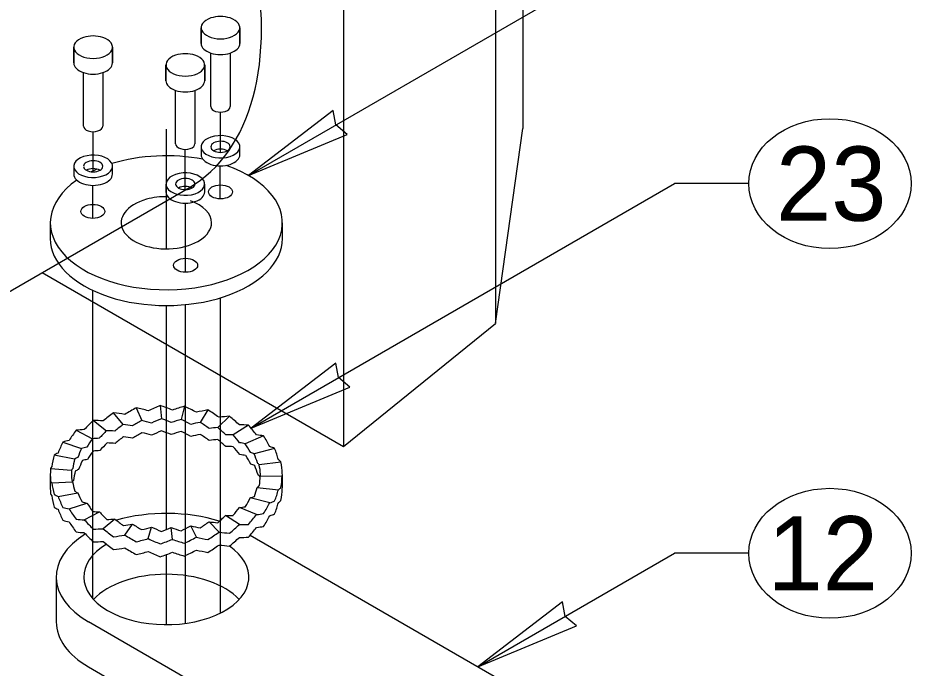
# Model space of a CAD drawing. Extents: x 99862 to 104211, y 98939 to 105076.
# Drawn here: x 102045.1 to 102237.6, y 101616.6 to 101756.7 of the extents above; entities that cross this region are included whole.
import ezdxf

# ---------------------------------------------------------------- set-up
doc = ezdxf.new("R2010")
doc.units = 0
for name, color, linetype in [('Level 11', 7, 'Continuous'), ('Level 12', 7, 'Continuous'), ('Level 15', 7, 'Continuous'), ('Level 19', 7, 'Continuous'), ('Level 20', 7, 'Continuous'), ('Level 24', 7, 'Continuous'), ('Level 26', 7, 'Continuous')]:
    doc.layers.add(name, color=color, linetype=linetype)

msp = doc.modelspace()

# ---------------------------------------------------------------- linework, layer by layer
at = {"layer": 'Level 11'}
for p, q in [((102084.64, 101751.2), (102084.64, 101754.6)), ((102084.64, 101754.6), (102084.64, 101751.2)), ((102092.98, 101754.6), (102092.98, 101751.2)), ((102092.98, 101751.2), (102092.98, 101754.6)), ((102057.2, 101747), (102057.2, 101750.4)), ((102057.2, 101750.4), (102057.2, 101747)), ((102065.54, 101750.4), (102065.54, 101747)), ((102065.54, 101747), (102065.54, 101750.4)), ((102086.73, 101737.59), (102086.73, 101749.12)), ((102090.89, 101749.12), (102090.89, 101737.59)), ((102077.06, 101743.17), (102077.06, 101746.58)), ((102077.06, 101746.58), (102077.06, 101743.17)), ((102085.4, 101746.58), (102085.4, 101743.17)), ((102085.4, 101743.17), (102085.4, 101746.58)), ((102059.29, 101733.39), (102059.29, 101744.91)), ((102063.45, 101744.91), (102063.45, 101733.39)), ((102079.15, 101729.57), (102079.15, 101741.09)), ((102083.31, 101741.09), (102083.31, 101729.57)), ((102084.64, 101728.93), (102084.64, 101727.23)), ((102092.98, 101727.23), (102092.98, 101728.93)), ((102057.2, 101724.73), (102057.2, 101723.03)), ((102065.54, 101723.03), (102065.54, 101724.73)), ((102077.06, 101720.9), (102077.06, 101719.2)), ((102085.4, 101719.2), (102085.4, 101720.9)), ((102052.14, 101712.56), (102052.14, 101709.16)), ((102102.14, 101709.16), (102102.14, 101712.56))]:
    msp.add_line(p, q, dxfattribs=at)
for centre, major_axis, start_param, end_param in [((102088.81, 101754.6), (-4.17, 0), 5.235988, 10.471976), ((102088.81, 101754.6), (-4.17, 0), 4.18879, 5.235988), ((102061.37, 101750.4), (-4.17, 0), 5.235988, 10.471976), ((102061.37, 101750.4), (-4.17, 0), 4.18879, 5.235988), ((102088.81, 101751.2), (-4.17, 0), 6.283185, 9.424778), ((102081.23, 101746.58), (-4.17, 0), 5.235988, 10.471976), ((102081.23, 101746.58), (-4.17, 0), 4.18879, 5.235988), ((102061.37, 101747), (-4.17, 0), 6.283185, 9.424778), ((102081.23, 101743.17), (-4.17, 0), 6.283185, 9.424778), ((102088.81, 101737.59), (-2.08, 0), 6.283129, 9.424778), ((102061.37, 101733.39), (-2.08, 0), 6.283129, 9.424778), ((102088.81, 101728.93), (-4.17, 0), 0.321913, 6.60445), ((102081.23, 101729.57), (-2.08, 0), 6.283129, 9.424778), ((102088.81, 101728.93), (-2.08, 0), 0.014662, 6.283185), ((102061.37, 101724.73), (-4.17, 0), 0.321913, 6.60445), ((102077.14, 101712.56), (-25, 0), 4.39277, 5.200653), ((102088.81, 101727.23), (-4.17, 0), 0, 3.141593), ((102088.81, 101727.23), (-2.08, 0), 3.926991, 5.497787), ((102061.37, 101724.73), (-2.08, 0), 0.014662, 6.283185), ((102077.14, 101712.56), (-25, 0), 5.593856, 10.454374), ((102061.37, 101723.03), (-2.08, 0), 3.926991, 5.497787), ((102077.14, 101712.56), (-25, 0), 5.35311, 5.417542), ((102081.23, 101720.9), (-4.17, 0), 0.321913, 6.60445), ((102061.37, 101723.03), (-4.17, 0), 0, 3.141593), ((102081.23, 101720.9), (-2.08, 0), 0.014662, 6.283185), ((102081.23, 101719.2), (-2.08, 0), 3.926991, 5.497787), ((102077.14, 101712.56), (9.74, 0), 2.024427, 6.283185), ((102077.14, 101712.56), (9.74, 0), 1.538326, 2.024427), ((102081.23, 101719.2), (-4.17, 0), 0, 3.141593), ((102077.14, 101712.56), (9.74, 0), 0, 1.006138), ((102077.14, 101709.16), (-25, 0), 0, 3.141593)]:
    msp.add_ellipse(centre, major_axis=major_axis, ratio=0.57735, start_param=start_param, end_param=end_param, dxfattribs=at)
for centre in [(102088.81, 101719.21), (102061.3, 101715.01), (102081.29, 101703.4)]:
    msp.add_ellipse(centre, major_axis=(-2.6, 0), ratio=0.57735, dxfattribs=at)
at = {"layer": 'Level 12'}
for p, q in [((102197.14, 101586.33), (102095.17, 101645.2)), ((102053.42, 101636.24), (102053.42, 101626.55)), ((102179.92, 101557.53), (102060.37, 101626.55)), ((102060.37, 101616.87), (102180.23, 101547.66))]:
    msp.add_line(p, q, dxfattribs=at)
for centre, major_axis, start_param, end_param in [((102077.14, 101636.24), (-23.72, 0), 4.210368, 5.182538), ((102077.14, 101636.24), (-23.72, 0), 5.538106, 7.068583), ((102077.14, 101636.24), (-17.79, 0), 5.523421, 10.132628), ((102077.14, 101626.55), (17.79, 0), 0.490883, 2.65071), ((102077.14, 101626.55), (23.72, 0), 3.141593, 3.926991)]:
    msp.add_ellipse(centre, major_axis=major_axis, ratio=0.57735, start_param=start_param, end_param=end_param, dxfattribs=at)
at = {"layer": 'Level 15'}
for p, q in [((102094.82, 101722.77), (102186.63, 101775.77)), ((102088.74, 101736.39), (102088.74, 101727.73)), ((102061.3, 101732.19), (102061.3, 101723.53)), ((102077.14, 101706.93), (102077.14, 101732.7)), ((102081.16, 101728.36), (102081.16, 101719.7)), ((102088.74, 101717.71), (102088.74, 101724.83)), ((102061.3, 101713.5), (102061.3, 101720.62)), ((102095.39, 101668.31), (102186.63, 101720.99)), ((102202.63, 101720.99), (102186.63, 101720.99)), ((102081.29, 101701.89), (102081.29, 101716.8)), ((102061.3, 101631.56), (102061.3, 101697.99)), ((102088.81, 101628.48), (102088.81, 101696.39)), ((102077.14, 101646.45), (102077.14, 101694.72)), ((102081.29, 101626.25), (102081.29, 101694.92)), ((102077.14, 101625.96), (102077.14, 101641.07)), ((102144.24, 101616.87), (102186.63, 101641.34)), ((102202.63, 101641.34), (102186.63, 101641.34))]:
    msp.add_line(p, q, dxfattribs=at)
for points in [[(102094.82, 101722.77), (102116.08, 101731.59), (102113.68, 101733.65), (102113.1, 101736.77)], [(102095.39, 101668.31), (102116.66, 101677.14), (102114.25, 101679.2), (102113.67, 101682.31)], [(102144.24, 101616.87), (102165.51, 101625.7), (102163.1, 101627.75), (102162.52, 101630.87)]]:
    msp.add_lwpolyline(points, close=True, dxfattribs=at)
at = {"layer": 'Level 19'}
for p, q in [((102148.09, 101690.86), (102153.96, 101732.86)), ((102115.32, 101664.37), (102148.09, 101690.86))]:
    msp.add_line(p, q, dxfattribs=at)
at = {"layer": 'Level 20'}
for centre in [(102220.13, 101720.99), (102220.13, 101641.34)]:
    msp.add_ellipse(centre, major_axis=(-17.5, 0), ratio=0.8, dxfattribs=at)
at = {"layer": 'Level 24'}
for p, q in [((102075.83, 101673.17), (102076.07, 101670.34)), ((102067.86, 101669.1), (102065.79, 101671.62)), ((102070.67, 101672.7), (102071.86, 101669.97)), ((102081.05, 101673.01), (102080.33, 101670.19)), ((102086.1, 101672.23), (102084.44, 101669.54)), ((102061.41, 101669.97), (102064.26, 101667.76)), ((102088.21, 101668.42), (102090.75, 101670.86)), ((102057.71, 101667.84), (102061.23, 101666.02)), ((102094.83, 101668.95), (102091.51, 101666.86)), ((102098.11, 101666.62), (102094.16, 101664.95)), ((102054.87, 101665.31), (102058.89, 101663.95)), ((102100.48, 101663.93), (102096.08, 101662.77)), ((102057.36, 101661.64), (102052.99, 101662.49)), ((102101.83, 101661.01), (102097.16, 101660.4)), ((102052.14, 101658.27), (102052.14, 101655.5)), ((102056.7, 101659.2), (102052.18, 101659.51)), ((102097.38, 101657.96), (102102.11, 101658)), ((102097.46, 101657.96), (102097.44, 101658.31)), ((102102.14, 101655.5), (102102.14, 101658.27)), ((102052.45, 101656.5), (102056.94, 101656.73)), ((102056.73, 101657.59), (102056.75, 101657.16)), ((102053.8, 101653.58), (102058.07, 101654.35)), ((102096.71, 101655.54), (102101.29, 101655.02)), ((102056.18, 101650.89), (102060.03, 101652.16)), ((102099.42, 101652.2), (102095.19, 101653.26)), ((102059.46, 101648.55), (102062.73, 101650.25)), ((102096.57, 101649.67), (102092.89, 101651.21)), ((102066.06, 101648.71), (102063.53, 101646.64)), ((102086.35, 101648.14), (102088.49, 101645.89)), ((102092.88, 101647.54), (102089.9, 101649.48)), ((102068.18, 101645.28), (102069.86, 101647.61)), ((102073.23, 101644.5), (102073.97, 101646.99)), ((102078.45, 101644.34), (102078.2, 101646.87)), ((102083.61, 101644.81), (102082.39, 101647.26))]:
    msp.add_line(p, q, dxfattribs=at)
for centre, major_axis, ratio, start_param, end_param in [((102077.14, 101657.78), (23.99, 13.35), 0.527399, 1.337713, 1.442432), ((102077.14, 101657.78), (-24.17, 12.86), 0.497899, 4.918981, 5.0237), ((102077.14, 101657.78), (23.09, 14.75), 0.650745, 1.648089, 1.752809), ((102077.14, 101657.78), (-24.67, 10.41), 0.386234, 5.240379, 5.345098), ((102077.14, 101657.78), (23.57, 14.17), 0.588004, 1.492908, 1.597627), ((102077.14, 101657.78), (-24.46, 11.73), 0.440657, 5.077658, 5.182378), ((102077.14, 101657.78), (24.32, 12.32), 0.468967, 1.180574, 1.285294), ((102077.14, 101657.78), (-23.79, 13.78), 0.557438, 4.763018, 4.867737), ((102077.14, 101657.78), (24.58, 11.09), 0.413044, 1.020027, 1.124747), ((102077.14, 101657.78), (-23.34, 14.49), 0.6191, 4.608118, 4.712837), ((102077.14, 101657.78), (22.56, 15.04), 0.715795, 1.806331, 1.911051), ((102077.14, 101657.78), (-24.82, 8.91), 0.335596, 5.40825, 5.512969), ((102077.09, 101657.78), (-18.71, -11.62), 0.598244, 4.622152, 4.729007), ((102077.09, 101657.81), (20.39, -9.75), 0.429328, 1.924562, 2.027518), ((102077.09, 101657.77), (-19.05, -10.93), 0.535491, 4.465396, 4.572456), ((102077.09, 101657.81), (20.16, -10.74), 0.484995, 1.769848, 1.872378), ((102077.09, 101657.77), (-19.34, -10.08), 0.475083, 4.306477, 4.413646), ((102077.09, 101657.81), (19.84, -11.56), 0.543025, 1.61865, 1.720863), ((102077.09, 101657.77), (-19.58, -9.08), 0.417364, 4.144071, 4.251256), ((102077.09, 101657.81), (19.43, -12.2), 0.603283, 1.46947, 1.571493), ((102077.14, 101657.78), (24.76, 9.68), 0.360362, 0.8552, 0.959575), ((102077.14, 101657.78), (-22.85, 14.83), 0.683288, 4.448984, 4.554049), ((102077.14, 101657.78), (22.09, 14.93), 0.783391, 1.973965, 2.078685), ((102077.14, 101657.78), (-24.91, 7.25), 0.290225, 5.582091, 5.686811), ((102077.09, 101657.79), (-17.89, -12.4), 0.730894, 4.937429, 5.043598), ((102077.09, 101657.8), (20.61, -7.34), 0.327453, 2.249442, 2.353465), ((102077.09, 101657.78), (-18.31, -12.12), 0.663313, 4.778515, 4.885072), ((102077.09, 101657.81), (20.54, -8.62), 0.376508, 2.084067, 2.18753), ((102077.19, 101655.99), (-18.89, -11.29), 0.566582, 4.65521, 4.761435), ((102077.2, 101655.96), (20.47, -9.2), 0.402516, 1.905515, 2.007935), ((102077.19, 101656), (-19.21, -10.52), 0.50498, 4.498422, 4.604994), ((102077.2, 101655.96), (20.29, -10.27), 0.456845, 1.749535, 1.851681), ((102077.19, 101656), (-19.47, -9.6), 0.445851, 4.33846, 4.445308), ((102077.2, 101655.96), (20.01, -11.17), 0.51373, 1.59739, 1.699385), ((102077.09, 101657.77), (-19.77, -7.94), 0.363082, 3.977435, 4.084195), ((102077.09, 101657.81), (18.96, -12.55), 0.66635, 1.317558, 1.419881), ((102077.14, 101657.78), (24.87, 8.06), 0.313871, 0.683714, 0.78878), ((102077.14, 101657.78), (-22.31, 15.05), 0.749264, 4.290148, 4.394522), ((102077.14, 101657.78), (-24.96, 5.45), 0.252109, 5.762237, 5.866957), ((102077.09, 101657.79), (-17.52, -12.37), 0.801277, 5.105481, 5.211183), ((102077.09, 101657.8), (20.62, -5.93), 0.283588, 2.42148, 2.526083), ((102077.19, 101655.99), (-18.51, -11.89), 0.630481, 4.810354, 4.916165), ((102077.2, 101655.96), (20.58, -7.99), 0.351433, 2.06656, 2.169358), ((102077.19, 101656), (-19.68, -8.52), 0.389728, 4.174109, 4.281154), ((102077.2, 101655.95), (19.64, -11.91), 0.572873, 1.447674, 1.549653), ((102077.19, 101656), (-19.85, -7.31), 0.337596, 4.00437, 4.11153), ((102077.2, 101655.95), (19.19, -12.45), 0.63428, 1.299034, 1.400798), ((102077.09, 101657.77), (-19.92, -6.63), 0.315205, 3.804372, 3.911664), ((102077.09, 101657.81), (18.4, -12.84), 0.731211, 1.168256, 1.269974), ((102077.14, 101657.78), (24.94, 6.37), 0.270119, 0.507084, 0.611804), ((102077.14, 101657.78), (-21.94, 14.64), 0.818147, 4.112606, 4.217325), ((102077.14, 101657.78), (21.92, 14.08), 0.853385, 2.16914, 2.27386), ((102077.09, 101657.79), (-17.45, -11.66), 0.874367, 5.304524, 5.409696), ((102077.09, 101657.79), (20.58, -4.42), 0.246838, 2.600485, 2.705657), ((102077.2, 101655.97), (20.61, -5.19), 0.264186, 2.407555, 2.51132), ((102077.19, 101655.99), (-18.1, -12.29), 0.696771, 4.966104, 5.071448), ((102077.2, 101655.97), (20.62, -6.65), 0.304762, 2.23369, 2.336945), ((102077.19, 101656), (-19.98, -5.95), 0.29281, 3.828548, 3.936073), ((102077.2, 101655.96), (18.7, -12.68), 0.698549, 1.144423, 1.247134), ((102077.09, 101657.77), (-20.04, -5.26), 0.270295, 3.626269, 3.732988), ((102077.09, 101657.81), (17.89, -12.71), 0.799628, 1.006665, 1.108934), ((102077.14, 101657.78), (24.98, 4.51), 0.236491, 0.323887, 0.428607), ((102077.14, 101657.78), (-22.18, 12.98), 0.888613, 3.882951, 3.987671), ((102077.14, 101657.78), (22.99, 10.64), 0.922162, 2.476441, 2.581161), ((102077.14, 101657.78), (-24.99, 3.53), 0.223561, 5.948263, 6.052982), ((102077.09, 101657.8), (-18.93, -7.75), 0.945022, 5.676186, 5.780789), ((102077.09, 101657.79), (20.52, -2.82), 0.219467, 2.786003, 2.891705), ((102077.19, 101655.98), (20.55, -3.63), 0.231835, 2.588195, 2.692495), ((102077.19, 101655.98), (-17.69, -12.44), 0.765721, 5.126739, 5.231572), ((102077.19, 101656), (-20.1, -4.52), 0.251785, 3.646437, 3.75321), ((102077.2, 101655.96), (18.13, -12.83), 0.765007, 0.991605, 1.094336), ((102077.09, 101657.77), (-20.15, -3.75), 0.235717, 3.442095, 3.548503), ((102077.09, 101657.81), (17.65, -11.94), 0.871239, 0.815178, 0.917775), ((102077.14, 101657.78), (-25, 1.53), 0.206802, 6.138761, 6.243481), ((102077.09, 101657.79), (20.44, -1.17), 0.203679, 2.976608, 3.082777), ((102077.19, 101655.98), (-17.41, -12.14), 0.837545, 5.303627, 5.407926), ((102077.19, 101655.99), (-20.2, -2.97), 0.222374, 3.458633, 3.565603), ((102077.2, 101655.96), (17.71, -12.45), 0.835077, 0.818447, 0.921647), ((102077.09, 101657.78), (-20.25, -2.16), 0.212017, 3.253154, 3.35918), ((102077.09, 101657.8), (18.83, -8.32), 0.941831, 0.468891, 0.57191), ((102077.14, 101657.78), (24.99, 2.54), 0.213589, 0.135385, 0.240105), ((102077.14, 101657.78), (-24.57, 4.88), 0.947565, 3.380043, 3.484762), ((102077.14, 101657.78), (-24.57, 4.88), 0.947565, 0.13373, 0.23845), ((102077.09, 101657.8), (18.83, -8.32), 0.941831, 3.50935, 3.613372), ((102077.2, 101655.97), (-17.81, -10.59), 0.911117, 5.546488, 5.650253), ((102077.19, 101655.98), (20.48, -2), 0.210005, 2.774764, 2.879597), ((102077.19, 101655.99), (-20.3, -1.34), 0.20486, 3.266696, 3.373414), ((102077.09, 101657.8), (-18.93, -7.75), 0.945022, 2.63741, 2.740916), ((102077.2, 101655.96), (17.89, -10.9), 0.907593, 0.67037, 0.687271), ((102077.09, 101657.78), (20.35, 0.51), 0.201051, 6.203047, 6.308631), ((102077.14, 101657.78), (22.99, 10.64), 0.922162, 5.722754, 5.827474), ((102077.14, 101657.78), (25, 0.51), 0.203365, 6.226668, 6.331388), ((102077.14, 101657.78), (25, 0.51), 0.203365, 3.189796, 3.294515), ((102077.14, 101657.78), (-22.18, 12.98), 0.888613, 0.636639, 0.741359), ((102077.09, 101657.78), (20.35, 0.51), 0.201051, 3.169927, 3.276484), ((102077.19, 101655.99), (20.39, -0.33), 0.200662, 2.965412, 3.034193), ((102077.09, 101657.81), (17.65, -11.94), 0.871239, 3.857172, 3.960635), ((102077.09, 101657.79), (20.44, -1.17), 0.203679, 6.011323, 6.116415), ((102077.14, 101655.99), (-24.57, -4.88), 0.947565, 6.097095, 6.149455), ((102077.14, 101655.99), (-25, -1.53), 0.206802, 0.039705, 0.144424), ((102077.14, 101657.78), (24.99, 2.54), 0.213589, 3.381698, 3.486418), ((102077.09, 101657.78), (-20.25, -2.16), 0.212017, 0.221451, 0.328307), ((102077.09, 101657.81), (17.89, -12.71), 0.799628, 4.049974, 4.152929), ((102077.09, 101657.79), (-17.45, -11.66), 0.874367, 2.267499, 2.37153), ((102077.14, 101657.78), (21.92, 14.08), 0.853385, 5.415452, 5.520172), ((102077.14, 101657.78), (-25, 1.53), 0.206802, 2.892449, 2.997168), ((102077.14, 101655.99), (-24.57, -4.88), 0.947565, 2.798423, 2.903143), ((102077.14, 101655.99), (25, -0.51), 0.203365, 6.234982, 6.287342), ((102077.14, 101655.99), (22.99, -10.64), 0.922162, 3.702024, 3.806744), ((102077.14, 101657.78), (-21.94, 14.64), 0.818147, 0.866293, 0.971013), ((102077.09, 101657.77), (-20.15, -3.75), 0.235717, 0.411581, 0.518641), ((102077.09, 101657.81), (18.4, -12.84), 0.731211, 4.212591, 4.315121), ((102077.09, 101657.79), (-17.52, -12.37), 0.801277, 2.070195, 2.174763), ((102077.09, 101657.79), (20.52, -2.82), 0.219467, 5.822424, 5.926992), ((102077.14, 101657.78), (22.09, 14.93), 0.783391, 5.220277, 5.324997), ((102077.14, 101657.78), (-24.99, 3.53), 0.223561, 2.70195, 2.80667), ((102077.14, 101655.99), (-22.18, -12.98), 0.888613, 2.295514, 2.400234), ((102077.14, 101655.99), (24.99, -2.54), 0.213589, 6.04308, 6.1478), ((102077.14, 101655.99), (-24.99, -3.53), 0.223561, 0.230203, 0.334923), ((102077.14, 101655.99), (21.92, -14.08), 0.853385, 4.009326, 4.114045), ((102077.14, 101657.78), (24.98, 4.51), 0.236491, 3.570199, 3.674919), ((102077.14, 101657.78), (-22.31, 15.05), 0.749264, 1.043836, 1.148555), ((102077.09, 101657.77), (-20.04, -5.26), 0.270295, 0.596668, 0.703484), ((102077.09, 101657.81), (18.96, -12.55), 0.66635, 4.362228, 4.464795), ((102077.09, 101657.79), (-17.89, -12.4), 0.730894, 1.903791, 2.008884), ((102077.09, 101657.79), (20.58, -4.42), 0.246838, 5.638651, 5.742681), ((102077.14, 101655.99), (-24.96, -5.45), 0.252109, 0.416228, 0.520948), ((102077.14, 101655.99), (22.09, -14.93), 0.783391, 4.204501, 4.308875), ((102077.14, 101657.78), (24.94, 6.37), 0.270119, 3.753396, 3.857771), ((102077.14, 101657.78), (-22.85, 14.83), 0.683288, 1.202326, 1.307392), ((102077.09, 101657.77), (-19.92, -6.63), 0.315205, 0.775717, 0.883239), ((102077.09, 101657.81), (19.43, -12.2), 0.603283, 4.515147, 4.616833), ((102077.09, 101657.78), (-18.71, -11.62), 0.598244, 1.591279, 1.697305), ((102077.09, 101657.8), (20.61, -7.34), 0.327453, 5.290905, 5.393923), ((102077.09, 101657.78), (-18.31, -12.12), 0.663313, 1.746368, 1.851952), ((102077.09, 101657.8), (20.62, -5.93), 0.283588, 5.461353, 5.564858), ((102077.14, 101657.78), (22.56, 15.04), 0.715795, 5.052644, 5.157364), ((102077.14, 101657.78), (-24.96, 5.45), 0.252109, 2.515925, 2.620645), ((102077.14, 101655.99), (-21.94, -14.64), 0.818147, 2.06586, 2.17058), ((102077.14, 101655.99), (24.98, -4.51), 0.236491, 5.854579, 5.959298), ((102077.14, 101657.78), (24.87, 8.06), 0.313871, 3.930372, 4.035437), ((102077.14, 101657.78), (-23.34, 14.49), 0.6191, 1.362151, 1.466525), ((102077.09, 101657.77), (-19.77, -7.94), 0.363082, 0.948373, 1.055486), ((102077.09, 101657.81), (19.84, -11.56), 0.543025, 4.663917, 4.765887), ((102077.09, 101657.77), (-19.58, -9.08), 0.417364, 1.115309, 1.222265), ((102077.09, 101657.81), (20.16, -10.74), 0.484995, 4.814659, 4.916713), ((102077.09, 101657.77), (-19.34, -10.08), 0.475083, 1.277326, 1.384046), ((102077.09, 101657.81), (20.39, -9.75), 0.429328, 4.968557, 5.070826), ((102077.09, 101657.77), (-19.05, -10.93), 0.535491, 1.435534, 1.541941), ((102077.09, 101657.81), (20.54, -8.62), 0.376508, 5.126927, 5.229524), ((102077.14, 101657.78), (23.09, 14.75), 0.650745, 4.894402, 4.999121), ((102077.14, 101657.78), (-24.91, 7.25), 0.290225, 2.335779, 2.440499), ((102077.14, 101655.99), (-22.31, -15.05), 0.749264, 1.888318, 1.993037), ((102077.14, 101655.99), (24.94, -6.37), 0.270119, 5.671382, 5.776101), ((102077.14, 101655.99), (-24.91, -7.21), 0.292084, 0.595944, 0.70101), ((102077.14, 101655.99), (22.6, -14.92), 0.716006, 4.368664, 4.47373), ((102077.14, 101657.78), (24.76, 9.68), 0.360362, 4.101167, 4.205887), ((102077.14, 101657.78), (-23.79, 13.78), 0.557438, 1.516705, 1.621425), ((102077.14, 101657.78), (24.58, 11.09), 0.413044, 4.266339, 4.371059), ((102077.14, 101657.78), (-24.17, 12.86), 0.497899, 1.672668, 1.777388), ((102077.14, 101657.78), (24.32, 12.32), 0.468967, 4.426886, 4.531606), ((102077.14, 101657.78), (-24.46, 11.73), 0.440657, 1.831346, 1.936066), ((102077.14, 101657.78), (23.99, 13.35), 0.527399, 4.584025, 4.688745), ((102077.14, 101657.78), (-24.67, 10.41), 0.386234, 1.994066, 2.098786), ((102077.14, 101657.78), (23.57, 14.17), 0.588004, 4.73922, 4.84394), ((102077.14, 101657.78), (-24.82, 8.91), 0.335596, 2.161937, 2.266657), ((102077.14, 101655.99), (-22.83, -14.93), 0.682966, 1.726553, 1.831273), ((102077.14, 101655.99), (24.87, -8.1), 0.312139, 5.494389, 5.599109), ((102077.14, 101655.99), (-24.82, -8.91), 0.335596, 0.770561, 0.874936), ((102077.14, 101655.99), (23.09, -14.75), 0.650745, 4.530376, 4.635096), ((102077.14, 101655.99), (-24.67, -10.41), 0.386234, 0.938087, 1.042807), ((102077.14, 101655.99), (23.57, -14.17), 0.588004, 4.685558, 4.790278), ((102077.14, 101655.99), (-23.34, -14.49), 0.6191, 1.570348, 1.675068), ((102077.14, 101655.99), (24.76, -9.68), 0.360362, 5.323611, 5.42833), ((102077.14, 101655.99), (-24.46, -11.73), 0.440657, 1.100807, 1.205527), ((102077.14, 101655.99), (23.99, -13.35), 0.527399, 4.840753, 4.945473), ((102077.14, 101655.99), (-24.17, -12.86), 0.497899, 1.259485, 1.364205), ((102077.14, 101655.99), (24.32, -12.32), 0.468967, 4.997892, 5.102611), ((102077.14, 101655.99), (-23.79, -13.78), 0.557438, 1.415448, 1.520168), ((102077.14, 101655.99), (24.58, -11.09), 0.413044, 5.158439, 5.263158)]:
    msp.add_ellipse(centre, major_axis=major_axis, ratio=ratio, start_param=start_param, end_param=end_param, dxfattribs=at)
at = {"layer": 'Level 26'}
for p, q in [((102153.96, 101882.14), (102153.96, 101732.86)), ((102148.09, 101844.85), (102148.09, 101690.86)), ((102115.32, 101825.93), (102115.32, 101664.37)), ((101997.26, 101671.16), (102082.11, 101720.15)), ((102050.41, 101701.85), (102115.32, 101664.37))]:
    msp.add_line(p, q, dxfattribs=at)
msp.add_ellipse((102044.61, 101785.11), major_axis=(37.5, -64.95), ratio=0.57735, start_param=0, end_param=3.141593, dxfattribs=at)

# ---------------------------------------------------------------- texts
at = {"layer": 'Level 20'}
for s, p in [('23', (102208.5, 101712.99)), ('12', (102206.69, 101633.34))]:
    msp.add_text(s, height=16, dxfattribs=at).set_placement(p)

doc.saveas('drawing.dxf')
